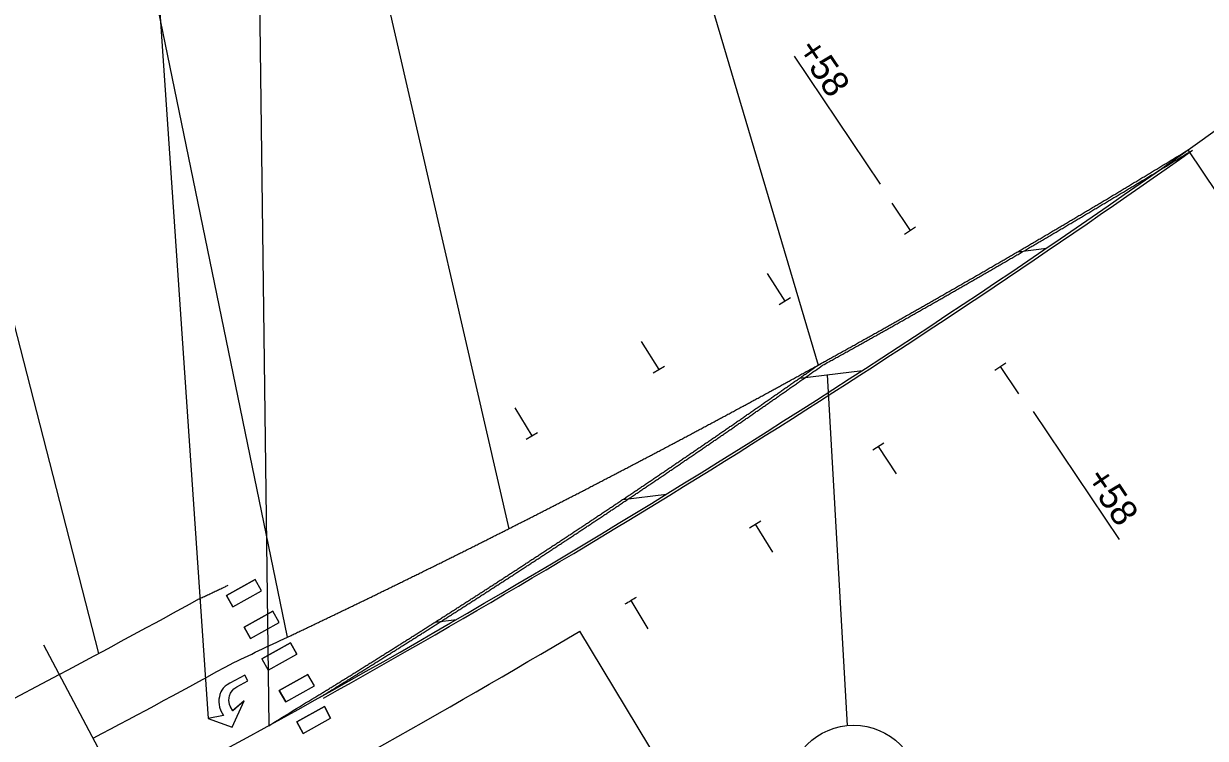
# Model space of a CAD drawing. Extents: x 1487421 to 1489048, y 497792 to 499463.
# Drawn here: x 1488099.3 to 1488279, y 498545.9 to 498654.5 of the extents above; entities that cross this region are included whole.
import ezdxf

# ---------------------------------------------------------------- set-up
doc = ezdxf.new("R2010")
doc.units = 0
for name, color, linetype in [('MARK LEFT TURN ARROW CELL', 7, 'Continuous'), ('Prop Dimension', 7, 'Continuous'), ('Prop Dimension Text', 7, 'Continuous'), ('Prop Mkg 3ft Min Skp 9ft White', 7, 'Continuous'), ('Prop Mkg Solid Dbl Yel Rpm 80ft', 7, 'Continuous'), ('Prop Mkg Solid Double Yellow', 7, 'Continuous'), ('Prop Mkg Solid White Lane Line', 7, 'Continuous'), ('Prop Mkg Solid Yellow Diagonals', 7, 'Continuous'), ('Prop Mkr Yel 20ft Spc', 7, 'Continuous'), ('Scratch_Level_3', 7, 'Continuous'), ('Scratch_Level_6', 7, 'Continuous'), ('Text', 7, 'Continuous')]:
    doc.layers.add(name, color=color, linetype=linetype)

msp = doc.modelspace()

# ---------------------------------------------------------------- linework, layer by layer
at = {"layer": 'MARK LEFT TURN ARROW CELL'}
for points in [[(1488133.43, 498554.61), (1488132.96, 498555.5), (1488130.68, 498554.29), (1488130.27, 498554.05), (1488129.98, 498553.82), (1488129.69, 498553.53), (1488129.47, 498553.22), (1488129.33, 498552.95), (1488129.17, 498552.54), (1488129.1, 498552.22), (1488129.03, 498551.84), (1488129, 498551.38), (1488129.04, 498551.05), (1488129.12, 498550.61), (1488129.33, 498550.06), (1488129.7, 498549.35), (1488127.4, 498548.89), (1488131.01, 498547.59), (1488132.86, 498551.58), (1488131.1, 498550.09), (1488130.79, 498550.68), (1488130.64, 498551.02), (1488130.56, 498551.37), (1488130.55, 498551.66), (1488130.56, 498552.07), (1488130.62, 498552.36), (1488130.79, 498552.75), (1488131.03, 498553.1), (1488131.3, 498553.4), (1488131.73, 498553.72)], [(1488133.43, 498554.61), (1488132.96, 498555.5), (1488130.68, 498554.29), (1488130.27, 498554.05), (1488129.98, 498553.82), (1488129.69, 498553.53), (1488129.48, 498553.22), (1488129.33, 498552.95), (1488129.17, 498552.54), (1488129.1, 498552.22), (1488129.03, 498551.84), (1488129, 498551.38), (1488129.04, 498551.05), (1488129.13, 498550.61), (1488129.33, 498550.06), (1488129.7, 498549.35), (1488127.41, 498548.89), (1488131.01, 498547.59), (1488132.86, 498551.58), (1488131.11, 498550.09), (1488130.79, 498550.68), (1488130.64, 498551.02), (1488130.56, 498551.37), (1488130.55, 498551.66), (1488130.57, 498552.07), (1488130.62, 498552.36), (1488130.79, 498552.75), (1488131.04, 498553.1), (1488131.3, 498553.4), (1488131.73, 498553.72)]]:
    msp.add_lwpolyline(points, close=True, dxfattribs=at)
at = {"layer": 'Prop Dimension'}
for p, q in [((1488216.48, 498649.56), (1488229.57, 498630.1)), ((1488252.8, 498595.55), (1488265.89, 498576.09)), ((1488115.05, 498536.17), (1488102.41, 498560.03))]:
    msp.add_line(p, q, dxfattribs=at)
at = {"layer": 'Prop Mkg 3ft Min Skp 9ft White'}
msp.add_arc((1487424.96, 499839.79), 1464, 297.89497, 298.84598, dxfattribs=at)
for points in [[(1488180.48, 498581.52), (1488181.14, 498581.86), (1488181.8, 498582.2), (1488182.46, 498582.53), (1488183.12, 498582.87), (1488183.78, 498583.21), (1488184.44, 498583.55), (1488185.1, 498583.89), (1488185.75, 498584.23), (1488186.41, 498584.58), (1488187.07, 498584.92), (1488187.73, 498585.26), (1488188.39, 498585.6), (1488189.04, 498585.94), (1488189.7, 498586.29), (1488190.36, 498586.63), (1488191.02, 498586.97), (1488191.67, 498587.32), (1488192.33, 498587.66), (1488192.99, 498588.01), (1488193.64, 498588.35), (1488194.3, 498588.7), (1488194.96, 498589.04), (1488195.61, 498589.39), (1488196.27, 498589.73), (1488196.92, 498590.08), (1488197.58, 498590.43), (1488198.24, 498590.78), (1488198.89, 498591.12), (1488199.55, 498591.47), (1488200.2, 498591.82), (1488200.86, 498592.17), (1488201.51, 498592.52), (1488202.17, 498592.87), (1488202.82, 498593.22), (1488203.47, 498593.57), (1488204.13, 498593.92), (1488204.78, 498594.27), (1488205.44, 498594.62), (1488206.09, 498594.97), (1488206.74, 498595.32), (1488207.4, 498595.67), (1488208.05, 498596.03), (1488208.7, 498596.38), (1488209.36, 498596.73), (1488210.01, 498597.09), (1488210.66, 498597.44), (1488211.31, 498597.79), (1488211.97, 498598.15), (1488212.62, 498598.5), (1488213.27, 498598.86), (1488213.92, 498599.21), (1488214.57, 498599.57), (1488215.23, 498599.93), (1488215.88, 498600.28), (1488216.53, 498600.64), (1488217.18, 498601), (1488217.83, 498601.36), (1488218.48, 498601.71), (1488219.13, 498602.07), (1488219.78, 498602.43), (1488220.14, 498602.63)], [(1488131.28, 498557.44), (1488139.98, 498561.53), (1488140.65, 498561.85), (1488141.32, 498562.17), (1488141.99, 498562.48), (1488142.65, 498562.8), (1488143.32, 498563.12), (1488143.99, 498563.44), (1488144.66, 498563.76), (1488145.32, 498564.08), (1488145.99, 498564.4), (1488146.66, 498564.72), (1488147.32, 498565.04), (1488147.99, 498565.36), (1488148.66, 498565.68), (1488149.32, 498566), (1488149.99, 498566.33), (1488150.66, 498566.65), (1488151.32, 498566.97), (1488151.99, 498567.29), (1488152.65, 498567.62), (1488153.32, 498567.94), (1488153.98, 498568.27), (1488154.65, 498568.59), (1488155.31, 498568.92), (1488155.98, 498569.24), (1488156.64, 498569.57), (1488157.31, 498569.89), (1488157.97, 498570.22), (1488158.64, 498570.55), (1488159.3, 498570.87), (1488159.97, 498571.2), (1488160.63, 498571.53), (1488161.29, 498571.85), (1488161.96, 498572.18), (1488162.62, 498572.51), (1488163.29, 498572.84), (1488163.95, 498573.17), (1488164.61, 498573.5), (1488165.27, 498573.83), (1488165.94, 498574.16), (1488166.6, 498574.49), (1488167.26, 498574.82), (1488167.93, 498575.15), (1488168.59, 498575.49), (1488169.25, 498575.82), (1488169.91, 498576.15), (1488170.57, 498576.48), (1488171.24, 498576.82), (1488171.9, 498577.15), (1488172.56, 498577.48), (1488173.22, 498577.82), (1488173.88, 498578.15), (1488174.54, 498578.49), (1488175.2, 498578.82), (1488175.86, 498579.16), (1488176.52, 498579.49), (1488177.18, 498579.83), (1488177.84, 498580.17), (1488178.5, 498580.5), (1488179.16, 498580.84), (1488179.82, 498581.18), (1488180.48, 498581.52)]]:
    msp.add_spline(points, degree=3, dxfattribs=at)
at = {"layer": 'Prop Mkg Solid Dbl Yel Rpm 80ft'}
msp.add_arc((1487424.96, 499839.79), 1475, 305.25533, 321.11565, dxfattribs=at)
at = {"layer": 'Prop Mkg Solid Double Yellow'}
msp.add_arc((1487424.96, 499839.79), 1475, 297.89497, 305.25533, dxfattribs=at)
for points in [[(1488228.87, 498607.49), (1488229.52, 498607.85), (1488230.16, 498608.21), (1488230.81, 498608.58), (1488231.46, 498608.94), (1488232.11, 498609.31), (1488232.75, 498609.67), (1488233.4, 498610.04), (1488234.05, 498610.41), (1488234.69, 498610.77), (1488235.34, 498611.14), (1488235.99, 498611.51), (1488236.63, 498611.87), (1488237.28, 498612.24), (1488237.93, 498612.61), (1488238.57, 498612.98), (1488239.22, 498613.35), (1488239.86, 498613.72), (1488240.51, 498614.09), (1488241.15, 498614.46), (1488241.8, 498614.83), (1488242.44, 498615.2), (1488243.09, 498615.57), (1488243.73, 498615.94), (1488244.37, 498616.31), (1488245.02, 498616.68), (1488245.66, 498617.05), (1488246.31, 498617.43), (1488246.95, 498617.8), (1488247.59, 498618.17), (1488248.24, 498618.55), (1488248.88, 498618.92), (1488249.52, 498619.3), (1488250.16, 498619.67), (1488250.81, 498620.04), (1488251.45, 498620.42), (1488252.09, 498620.8), (1488252.73, 498621.17), (1488253.37, 498621.55), (1488254.02, 498621.92), (1488254.66, 498622.3), (1488255.3, 498622.68), (1488255.94, 498623.06), (1488256.58, 498623.43), (1488257.22, 498623.81), (1488257.86, 498624.19), (1488258.5, 498624.57), (1488259.14, 498624.95), (1488259.78, 498625.33), (1488260.42, 498625.71), (1488261.06, 498626.09), (1488261.7, 498626.47), (1488262.34, 498626.85), (1488262.98, 498627.23), (1488263.62, 498627.61), (1488264.26, 498628), (1488264.9, 498628.38), (1488265.54, 498628.76), (1488266.18, 498629.14), (1488266.81, 498629.53), (1488267.45, 498629.91), (1488268.09, 498630.3), (1488268.73, 498630.68), (1488269.36, 498631.06), (1488270, 498631.45), (1488270.64, 498631.84), (1488271.28, 498632.22), (1488271.91, 498632.61), (1488272.55, 498632.99), (1488273.19, 498633.38), (1488273.82, 498633.77), (1488274.46, 498634.15), (1488275.09, 498634.54), (1488276.37, 498635.32)], [(1488220.14, 498602.63), (1488221.08, 498603.15), (1488221.73, 498603.51), (1488222.38, 498603.87), (1488223.03, 498604.23), (1488223.68, 498604.59), (1488224.33, 498604.95), (1488224.98, 498605.31), (1488225.63, 498605.67), (1488226.28, 498606.04), (1488226.92, 498606.4), (1488227.57, 498606.76), (1488228.22, 498607.12), (1488228.87, 498607.49)], [(1488178.86, 498574.53), (1488179.42, 498574.9), (1488179.99, 498575.27), (1488180.55, 498575.64), (1488181.12, 498576.01), (1488181.68, 498576.38), (1488182.24, 498576.75), (1488182.81, 498577.13), (1488183.37, 498577.5), (1488183.93, 498577.87), (1488184.5, 498578.24), (1488185.06, 498578.62), (1488185.62, 498578.99), (1488186.18, 498579.36), (1488186.74, 498579.74), (1488187.31, 498580.11), (1488187.87, 498580.49), (1488188.43, 498580.86), (1488188.99, 498581.24), (1488189.55, 498581.61), (1488190.11, 498581.99), (1488190.67, 498582.36), (1488191.24, 498582.74), (1488191.8, 498583.11), (1488192.36, 498583.49), (1488192.92, 498583.87), (1488193.48, 498584.24), (1488194.04, 498584.62), (1488194.6, 498585), (1488195.16, 498585.38), (1488195.71, 498585.75), (1488196.27, 498586.13), (1488196.83, 498586.51), (1488197.39, 498586.89), (1488197.95, 498587.27), (1488198.51, 498587.65), (1488199.07, 498588.03), (1488199.62, 498588.41), (1488200.18, 498588.79), (1488200.74, 498589.17), (1488201.3, 498589.55), (1488201.85, 498589.93), (1488202.41, 498590.31), (1488202.97, 498590.69), (1488203.52, 498591.07), (1488204.08, 498591.45), (1488204.64, 498591.83), (1488205.19, 498592.22), (1488205.75, 498592.6), (1488206.3, 498592.98), (1488206.86, 498593.36), (1488207.42, 498593.75), (1488207.97, 498594.13), (1488208.53, 498594.51), (1488209.08, 498594.9), (1488209.63, 498595.28), (1488210.19, 498595.67), (1488210.74, 498596.05), (1488211.3, 498596.44), (1488211.85, 498596.82), (1488212.4, 498597.21), (1488212.96, 498597.59), (1488213.51, 498597.98), (1488214.06, 498598.36), (1488214.62, 498598.75), (1488215.17, 498599.14), (1488215.72, 498599.52), (1488216.27, 498599.91), (1488216.83, 498600.3), (1488217.38, 498600.68), (1488217.93, 498601.07), (1488218.48, 498601.46), (1488219.03, 498601.85), (1488220.14, 498602.63)], [(1488136.59, 498547.8), (1488144.08, 498552.4), (1488144.66, 498552.75), (1488145.23, 498553.11), (1488145.81, 498553.46), (1488146.38, 498553.82), (1488146.96, 498554.17), (1488147.53, 498554.53), (1488148.11, 498554.89), (1488148.68, 498555.24), (1488149.26, 498555.6), (1488149.83, 498555.96), (1488150.4, 498556.32), (1488150.98, 498556.68), (1488151.55, 498557.03), (1488152.12, 498557.39), (1488152.7, 498557.75), (1488153.27, 498558.11), (1488153.84, 498558.47), (1488154.41, 498558.83), (1488154.99, 498559.19), (1488155.56, 498559.55), (1488156.13, 498559.91), (1488156.7, 498560.27), (1488157.27, 498560.63), (1488157.84, 498560.99), (1488158.42, 498561.35), (1488158.99, 498561.71), (1488159.56, 498562.07), (1488160.13, 498562.44), (1488160.7, 498562.8), (1488161.27, 498563.16), (1488161.84, 498563.52), (1488162.41, 498563.89), (1488162.98, 498564.25), (1488163.55, 498564.61), (1488164.12, 498564.98), (1488164.69, 498565.34), (1488165.26, 498565.71), (1488165.82, 498566.07), (1488166.39, 498566.44), (1488166.96, 498566.8), (1488167.53, 498567.17), (1488168.1, 498567.53), (1488168.67, 498567.9), (1488169.23, 498568.26), (1488169.8, 498568.63), (1488170.37, 498569), (1488170.94, 498569.36), (1488171.5, 498569.73), (1488172.07, 498570.1), (1488172.64, 498570.47), (1488173.2, 498570.83), (1488173.77, 498571.2), (1488174.34, 498571.57), (1488174.9, 498571.94), (1488175.47, 498572.31), (1488176.03, 498572.68), (1488176.6, 498573.05), (1488177.16, 498573.42), (1488177.73, 498573.79), (1488178.29, 498574.16), (1488178.86, 498574.53)]]:
    msp.add_spline(points, degree=3, dxfattribs=at)
at = {"layer": 'Prop Mkg Solid White Lane Line'}
for p, q in [((1488231.32, 498627.22), (1488234.09, 498623.06)), ((1488233.25, 498622.5), (1488234.92, 498623.61)), ((1488212.35, 498616.56), (1488215.06, 498612.36)), ((1488214.22, 498611.82), (1488215.9, 498612.9)), ((1488193.24, 498606.2), (1488195.89, 498601.96)), ((1488195.04, 498601.43), (1488196.74, 498602.48)), ((1488246.99, 498601.85), (1488248.65, 498602.96)), ((1488247.82, 498602.41), (1488250.59, 498598.24)), ((1488174, 498596.14), (1488176.58, 498591.85)), ((1488175.73, 498591.34), (1488177.44, 498592.37)), ((1488228.43, 498589.73), (1488230.11, 498590.81)), ((1488229.27, 498590.27), (1488231.98, 498586.07)), ((1488209.7, 498577.89), (1488211.4, 498578.94)), ((1488210.55, 498578.42), (1488213.19, 498574.17)), ((1488191.65, 498566.84), (1488194.23, 498562.56))]:
    msp.add_line(p, q, dxfattribs=at)
msp.add_arc((1487424.96, 499839.79), 1486, 301.02156, 301.09867, dxfattribs=at)
at = {"layer": 'Prop Mkg Solid Yellow Diagonals'}
for p, q in [((1488250.47, 498619.85), (1488254.84, 498620.39)), ((1488217.3, 498600.63), (1488226.87, 498601.81)), ((1488190.42, 498582.19), (1488197.07, 498583.01)), ((1488161.87, 498563.55), (1488165.15, 498563.95))]:
    msp.add_line(p, q, dxfattribs=at)
at = {"layer": 'Prop Mkr Yel 20ft Spc'}
msp.add_arc((1487425.64, 499839.75), 1475, 299.18581, 305.25533, dxfattribs=at)
for points in [[(1488229.54, 498607.46), (1488230.19, 498607.82), (1488230.84, 498608.18), (1488231.48, 498608.55), (1488232.13, 498608.91), (1488232.78, 498609.28), (1488233.43, 498609.64), (1488234.07, 498610.01), (1488234.72, 498610.38), (1488235.37, 498610.74), (1488236.01, 498611.11), (1488236.66, 498611.48), (1488237.31, 498611.84), (1488237.95, 498612.21), (1488238.6, 498612.58), (1488239.24, 498612.95), (1488239.89, 498613.32), (1488240.53, 498613.69), (1488241.18, 498614.06), (1488241.82, 498614.43), (1488242.47, 498614.8), (1488243.11, 498615.17), (1488243.76, 498615.54), (1488244.4, 498615.91), (1488245.05, 498616.28), (1488245.69, 498616.65), (1488246.33, 498617.02), (1488246.98, 498617.4), (1488247.62, 498617.77), (1488248.26, 498618.14), (1488248.91, 498618.52), (1488249.55, 498618.89), (1488250.19, 498619.26), (1488250.84, 498619.64), (1488251.48, 498620.01), (1488252.12, 498620.39), (1488252.76, 498620.77), (1488253.41, 498621.14), (1488254.05, 498621.52), (1488254.69, 498621.89), (1488255.33, 498622.27), (1488255.97, 498622.65), (1488256.61, 498623.03), (1488257.25, 498623.4), (1488257.89, 498623.78), (1488258.53, 498624.16), (1488259.18, 498624.54), (1488259.82, 498624.92), (1488260.46, 498625.3), (1488261.1, 498625.68), (1488261.74, 498626.06), (1488262.37, 498626.44), (1488263.01, 498626.82), (1488263.65, 498627.2), (1488264.29, 498627.58), (1488264.93, 498627.97), (1488265.57, 498628.35), (1488266.21, 498628.73), (1488266.85, 498629.11), (1488267.49, 498629.5), (1488268.12, 498629.88), (1488268.76, 498630.27), (1488269.4, 498630.65), (1488270.04, 498631.03), (1488270.67, 498631.42), (1488271.31, 498631.8), (1488271.95, 498632.19), (1488272.59, 498632.58), (1488273.22, 498632.96), (1488273.86, 498633.35), (1488274.49, 498633.74), (1488275.13, 498634.12), (1488275.77, 498634.51), (1488277.04, 498635.29)], [(1488220.81, 498602.6), (1488221.75, 498603.12), (1488222.4, 498603.48), (1488223.05, 498603.84), (1488223.7, 498604.2), (1488224.35, 498604.56), (1488225, 498604.92), (1488225.65, 498605.28), (1488226.3, 498605.64), (1488226.95, 498606), (1488227.6, 498606.37), (1488228.24, 498606.73), (1488228.89, 498607.09), (1488229.54, 498607.46)], [(1488179.53, 498574.5), (1488180.09, 498574.87), (1488180.66, 498575.24), (1488181.22, 498575.61), (1488181.79, 498575.98), (1488182.35, 498576.35), (1488182.91, 498576.72), (1488183.48, 498577.09), (1488184.04, 498577.47), (1488184.6, 498577.84), (1488185.17, 498578.21), (1488185.73, 498578.59), (1488186.29, 498578.96), (1488186.85, 498579.33), (1488187.42, 498579.71), (1488187.98, 498580.08), (1488188.54, 498580.46), (1488189.1, 498580.83), (1488189.66, 498581.2), (1488190.22, 498581.58), (1488190.79, 498581.96), (1488191.35, 498582.33), (1488191.91, 498582.71), (1488192.47, 498583.08), (1488193.03, 498583.46), (1488193.59, 498583.84), (1488194.15, 498584.21), (1488194.71, 498584.59), (1488195.27, 498584.97), (1488195.83, 498585.35), (1488196.39, 498585.72), (1488196.95, 498586.1), (1488197.5, 498586.48), (1488198.06, 498586.86), (1488198.62, 498587.24), (1488199.18, 498587.62), (1488199.74, 498588), (1488200.3, 498588.38), (1488200.85, 498588.75), (1488201.41, 498589.14), (1488201.97, 498589.52), (1488202.53, 498589.9), (1488203.08, 498590.28), (1488203.64, 498590.66), (1488204.2, 498591.04), (1488204.75, 498591.42), (1488205.31, 498591.8), (1488205.86, 498592.19), (1488206.42, 498592.57), (1488206.98, 498592.95), (1488207.53, 498593.33), (1488208.09, 498593.72), (1488208.64, 498594.1), (1488209.2, 498594.48), (1488209.75, 498594.87), (1488210.31, 498595.25), (1488210.86, 498595.64), (1488211.42, 498596.02), (1488211.97, 498596.4), (1488212.52, 498596.79), (1488213.08, 498597.18), (1488213.63, 498597.56), (1488214.18, 498597.95), (1488214.74, 498598.33), (1488215.29, 498598.72), (1488215.84, 498599.11), (1488216.39, 498599.49), (1488216.95, 498599.88), (1488217.5, 498600.27), (1488218.05, 498600.65), (1488218.6, 498601.04), (1488219.15, 498601.43), (1488219.71, 498601.82), (1488220.81, 498602.6)], [(1488144.24, 498552.05), (1488144.76, 498552.37), (1488145.33, 498552.72), (1488145.91, 498553.08), (1488146.48, 498553.43), (1488147.06, 498553.79), (1488147.63, 498554.14), (1488148.21, 498554.5), (1488148.78, 498554.86), (1488149.35, 498555.21), (1488149.93, 498555.57), (1488150.5, 498555.93), (1488151.08, 498556.29), (1488151.65, 498556.64), (1488152.22, 498557), (1488152.8, 498557.36), (1488153.37, 498557.72), (1488153.94, 498558.08), (1488154.51, 498558.44), (1488155.09, 498558.8), (1488155.66, 498559.16), (1488156.23, 498559.52), (1488156.8, 498559.88), (1488157.37, 498560.24), (1488157.95, 498560.6), (1488158.52, 498560.96), (1488159.09, 498561.32), (1488159.66, 498561.68), (1488160.23, 498562.04), (1488160.8, 498562.41), (1488161.37, 498562.77), (1488161.94, 498563.13), (1488162.51, 498563.49), (1488163.08, 498563.86), (1488163.65, 498564.22), (1488164.22, 498564.58), (1488164.79, 498564.95), (1488165.36, 498565.31), (1488165.93, 498565.68), (1488166.5, 498566.04), (1488167.07, 498566.41), (1488167.63, 498566.77), (1488168.2, 498567.14), (1488168.77, 498567.5), (1488169.34, 498567.87), (1488169.91, 498568.23), (1488170.47, 498568.6), (1488171.04, 498568.97), (1488171.61, 498569.33), (1488172.17, 498569.7), (1488172.74, 498570.07), (1488173.31, 498570.43), (1488173.88, 498570.8), (1488174.44, 498571.17), (1488175.01, 498571.54), (1488175.57, 498571.91), (1488176.14, 498572.28), (1488176.7, 498572.65), (1488177.27, 498573.02), (1488177.84, 498573.38), (1488178.4, 498573.75), (1488178.97, 498574.12), (1488179.53, 498574.5)]]:
    msp.add_spline(points, degree=3, dxfattribs=at)
at = {"layer": 'Scratch_Level_3'}
for p, q in [((1488130.17, 498567.61), (1488134.54, 498570.04)), ((1488134.54, 498570.04), (1488130.17, 498567.61)), ((1488135.51, 498568.3), (1488134.54, 498570.04)), ((1488135.51, 498568.3), (1488134.54, 498570.04)), ((1488131.14, 498565.87), (1488130.17, 498567.61)), ((1488130.17, 498567.61), (1488131.14, 498565.87)), ((1488131.14, 498565.87), (1488135.51, 498568.3)), ((1488131.14, 498565.87), (1488135.51, 498568.3)), ((1488132.85, 498562.81), (1488137.21, 498565.24)), ((1488137.21, 498565.24), (1488132.85, 498562.81)), ((1488133.82, 498561.06), (1488138.19, 498563.49)), ((1488133.82, 498561.06), (1488138.19, 498563.49)), ((1488138.19, 498563.49), (1488137.21, 498565.24)), ((1488138.19, 498563.49), (1488137.21, 498565.24)), ((1488133.82, 498561.06), (1488132.85, 498562.81)), ((1488132.85, 498562.81), (1488133.82, 498561.06)), ((1488135.52, 498558), (1488139.89, 498560.43)), ((1488139.89, 498560.43), (1488135.52, 498558)), ((1488139.89, 498560.43), (1488140.86, 498558.68)), ((1488140.86, 498558.68), (1488139.89, 498560.43)), ((1488136.49, 498556.25), (1488140.86, 498558.68)), ((1488136.49, 498556.25), (1488140.86, 498558.68)), ((1488135.52, 498558), (1488136.49, 498556.25)), ((1488135.52, 498558), (1488136.49, 498556.25)), ((1488138.19, 498553.19), (1488142.56, 498555.62)), ((1488142.56, 498555.62), (1488138.19, 498553.19)), ((1488143.53, 498553.88), (1488142.56, 498555.62)), ((1488143.53, 498553.88), (1488142.56, 498555.62)), ((1488139.17, 498551.45), (1488138.19, 498553.19)), ((1488138.19, 498553.19), (1488139.17, 498551.45)), ((1488139.17, 498551.45), (1488143.53, 498553.88)), ((1488139.17, 498551.45), (1488143.53, 498553.88)), ((1488140.87, 498548.39), (1488145.05, 498550.72)), ((1488145.05, 498550.72), (1488140.87, 498548.39)), ((1488145.05, 498550.72), (1488145.99, 498548.95)), ((1488145.99, 498548.95), (1488145.05, 498550.72)), ((1488141.84, 498546.64), (1488140.87, 498548.39)), ((1488140.87, 498548.39), (1488141.84, 498546.64)), ((1488141.84, 498546.64), (1488145.99, 498548.95)), ((1488141.84, 498546.64), (1488145.99, 498548.95))]:
    msp.add_line(p, q, dxfattribs=at)
msp.add_spline([(1488125.97, 498567.07), (1488126.64, 498567.38), (1488127.3, 498567.69), (1488127.97, 498568.01), (1488128.63, 498568.32), (1488129.3, 498568.63), (1488129.96, 498568.94), (1488130.45, 498569.17)], degree=3, dxfattribs=at)
at = {"layer": 'Scratch_Level_6'}
for p, q in [((1488107.44, 498716.37), (1488139.41, 498561.26)), ((1488087.84, 498647.78), (1488110.69, 498558.78)), ((1488222.16, 498498.93), (1488183.88, 498562.19)), ((1488010.18, 498505.55), (1488104.75, 498555.61))]:
    msp.add_line(p, q, dxfattribs=at)
for radius, end in [(1453, 298.84598), (1486, 300.71095)]:
    msp.add_arc((1487424.96, 499839.79), radius, 297.89497, end, dxfattribs=at)
at = {"layer": 'Text'}
for p, q in [((1488115.27, 498725.46), (1488127.41, 498548.89)), ((1488185.47, 498719.43), (1488220.14, 498602.63)), ((1488134.42, 498717.1), (1488136.59, 498547.8)), ((1488152.35, 498667.96), (1488173.09, 498577.75)), ((1488315.5, 498577.12), (1488276.37, 498635.32)), ((1488224.57, 498547.84), (1488221.54, 498601.15))]:
    msp.add_line(p, q, dxfattribs=at)
msp.add_circle((1488225.52, 498537.88), 10, dxfattribs=at)

# ---------------------------------------------------------------- texts
at = {"layer": 'Prop Dimension Text'}
for p in [(1488216.81, 498650.54), (1488260.68, 498585.36)]:
    msp.add_text('+58', height=4, rotation=303.9186, dxfattribs=at).set_placement(p)

doc.saveas('drawing.dxf')
